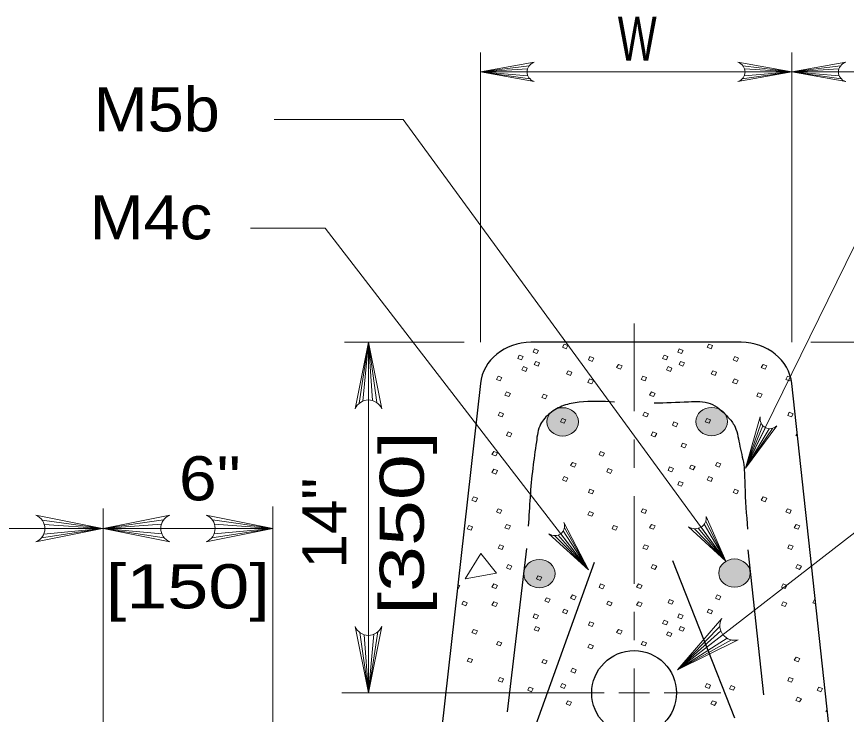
# Model space of a CAD drawing. Extents: x 1083.1 to 1123, y 697.4 to 741.4.
# Drawn here: x 1091.119 to 1094.054, y 706.055 to 708.522 of the extents above; entities that cross this region are included whole.
import ezdxf
from ezdxf.enums import TextEntityAlignment as Align

# ---------------------------------------------------------------- set-up
doc = ezdxf.new("R2010")
doc.units = 0
doc.header["$LTSCALE"] = 0.062
doc.linetypes.add('DOT_DASHED', pattern=[7.7, 5, -1.2, 0.3, -1.2])
doc.layers.add('1', color=7, linetype='Continuous', lineweight=13)

msp = doc.modelspace()

# ---------------------------------------------------------------- hatches: boundary and pattern name
at = {"layer": '1'}
h = msp.add_hatch(color=256, dxfattribs=at)
edge = h.paths.add_edge_path()
edge.add_ellipse((1093.05029, 707.08925), major_axis=(0.05572, 0), ratio=0.8999053, start_angle=0, end_angle=360)
h = msp.add_hatch(color=256, dxfattribs=at)
edge = h.paths.add_edge_path()
edge.add_ellipse((1093.57724, 707.09022), major_axis=(0.05572, 0), ratio=0.8999053, start_angle=0, end_angle=360)
h = msp.add_hatch(color=256, dxfattribs=at)
edge = h.paths.add_edge_path()
edge.add_ellipse((1092.96803, 706.55274), major_axis=(0.05572, 0), ratio=0.8999053, start_angle=0, end_angle=360)
h = msp.add_hatch(color=256, dxfattribs=at)
edge = h.paths.add_edge_path()
edge.add_ellipse((1093.65788, 706.55452), major_axis=(0.05572, 0), ratio=0.8999053, start_angle=0, end_angle=360)

# ---------------------------------------------------------------- linework, layer by layer
for p, q in [((1092.759, 707.3705), (1092.759, 708.39542)), ((1093.86025, 707.3705), (1093.86025, 708.39542)), ((1092.93175, 708.34817), (1092.759, 708.32642)), ((1092.92592, 708.33742), (1092.759, 708.32642)), ((1093.6875, 708.34817), (1093.86025, 708.32642)), ((1093.69333, 708.33742), (1093.86025, 708.32642)), ((1094.033, 708.34817), (1093.86025, 708.32642)), ((1094.02717, 708.33742), (1093.86025, 708.32642)), ((1092.92417, 708.32642), (1092.759, 708.32642)), ((1092.92717, 708.3125), (1092.759, 708.32642)), ((1092.93383, 708.30242), (1092.759, 708.32642)), ((1093.68542, 708.30242), (1093.86025, 708.32642)), ((1093.69208, 708.3125), (1093.86025, 708.32642)), ((1093.69508, 708.32642), (1093.86025, 708.32642)), ((1094.02533, 708.32642), (1093.86025, 708.32642)), ((1094.02842, 708.3125), (1093.86025, 708.32642)), ((1094.035, 708.30242), (1093.86025, 708.32642)), ((1092.02992, 708.158), (1092.48667, 708.158)), ((1093.62725, 706.59642), (1092.48667, 708.158)), ((1093.45608, 706.21192), (1095.83508, 708.05542)), ((1092.21067, 707.77358), (1091.94575, 707.77358)), ((1093.141, 706.5665), (1092.21067, 707.77358)), ((1092.70183, 707.3705), (1092.27875, 707.3705)), ((1092.33, 707.15475), (1092.363, 707.3705)), ((1092.34383, 707.16292), (1092.363, 707.3705)), ((1092.363, 706.13058), (1092.363, 707.3705)), ((1092.363, 707.16667), (1092.363, 707.3705)), ((1092.37808, 707.16442), (1092.363, 707.3705)), ((1092.39283, 707.15725), (1092.363, 707.3705)), ((1093.92825, 707.3705), (1096.348, 707.3705)), ((1093.84525, 707.25058), (1093.851, 707.2485)), ((1093.75167, 707.08575), (1093.69625, 706.92575)), ((1093.75833, 707.07567), (1093.69625, 706.92575)), ((1093.767, 707.069), (1093.69625, 706.92575)), ((1093.79175, 707.06617), (1093.69625, 706.92575)), ((1093.78033, 707.06508), (1093.69625, 706.92575)), ((1091.42492, 704.693), (1091.42492, 706.78342)), ((1092.02483, 704.99242), (1092.02483, 706.78958)), ((1091.20958, 706.74158), (1091.42292, 706.71175)), ((1091.21683, 706.72683), (1091.42292, 706.71175)), ((1091.63825, 706.74233), (1091.42492, 706.7125)), ((1091.631, 706.7275), (1091.42492, 706.7125)), ((1091.8115, 706.74233), (1092.02483, 706.7125)), ((1091.81875, 706.7275), (1092.02483, 706.7125)), ((1093.53975, 706.71725), (1093.62725, 706.59642)), ((1093.55067, 706.72692), (1093.62725, 706.59642)), ((1093.55633, 706.737), (1093.62725, 706.59642)), ((1091.42292, 706.71175), (1087.15183, 706.71308)), ((1091.20708, 706.67883), (1091.42292, 706.71175)), ((1091.21525, 706.69258), (1091.42292, 706.71175)), ((1091.21908, 706.71175), (1091.42292, 706.71175)), ((1091.42492, 706.7125), (1092.02483, 706.7125)), ((1091.62883, 706.7125), (1091.42492, 706.7125)), ((1091.63258, 706.69333), (1091.42492, 706.7125)), ((1091.64075, 706.6795), (1091.42492, 706.7125)), ((1091.809, 706.6795), (1092.02483, 706.7125)), ((1091.81717, 706.69333), (1092.02483, 706.7125)), ((1091.821, 706.7125), (1092.02483, 706.7125)), ((1093.022, 706.68667), (1093.141, 706.5665)), ((1093.03375, 706.6885), (1093.141, 706.5665)), ((1093.04333, 706.6935), (1093.141, 706.5665)), ((1093.05233, 706.70408), (1093.141, 706.5665)), ((1093.05617, 706.71508), (1093.141, 706.5665)), ((1093.51608, 706.71142), (1093.62725, 706.59642)), ((1093.52883, 706.71283), (1093.62725, 706.59642)), ((1093.94042, 706.46108), (1093.94367, 706.45967)), ((1093.60642, 706.36617), (1093.45608, 706.21192)), ((1092.33317, 706.34392), (1092.363, 706.13058)), ((1092.34792, 706.33667), (1092.363, 706.13058)), ((1092.396, 706.34642), (1092.363, 706.13058)), ((1092.38217, 706.33825), (1092.363, 706.13058)), ((1092.363, 706.3345), (1092.363, 706.13058)), ((1093.60975, 706.35008), (1093.45608, 706.21192)), ((1093.61725, 706.33683), (1093.45608, 706.21192)), ((1093.63192, 706.324), (1093.45608, 706.21192)), ((1093.64683, 706.31808), (1093.45608, 706.21192)), ((1093.19725, 706.13058), (1092.26917, 706.13058)), ((1093.357, 706.13058), (1093.24842, 706.13058)), ((1093.6095, 706.13058), (1093.4095, 706.13058))]:
    msp.add_line(p, q, dxfattribs=at)
at = {"layer": '1', "linetype": 'DOT_DASHED'}
msp.add_line((1093.30267, 707.43708), (1093.30267, 704.80367), dxfattribs=at)
at = {"layer": '1', "lineweight": 25}
for p, q in [((1093.68158, 707.3705), (1092.93775, 707.3705)), ((1092.92267, 706.64133), (1092.854, 706.06392)), ((1093.70475, 706.63675), (1093.76025, 706.12408)), ((1093.16208, 706.59233), (1092.73708, 705.41425)), ((1093.65925, 706.04117), (1093.43958, 706.5975))]:
    msp.add_line(p, q, dxfattribs=at)
at = {"layer": '1'}
for points in [[(1092.94983, 708.29208), (1092.759, 708.32642), (1092.94983, 708.36083)], [(1093.66942, 708.29208), (1093.86025, 708.32642), (1093.66942, 708.36083)], [(1094.05108, 708.29208), (1093.86025, 708.32642), (1094.05108, 708.36083)], [(1095.16083, 708.32642), (1093.50392, 708.32642), (1092.759, 708.32642)], [(1093.70142, 706.93558), (1094.084, 707.71383), (1094.26242, 707.71383)], [(1092.31592, 707.13492), (1092.363, 707.3705), (1092.41008, 707.13492)], [(1093.85508, 707.23808), (1093.85333, 707.23442), (1093.83983, 707.23925), (1093.84525, 707.25058)], [(1093.80742, 707.07525), (1093.69625, 706.92575), (1093.74858, 707.10725)], [(1093.88042, 707.03925), (1093.87492, 707.04125), (1093.87925, 707.04983)], [(1091.18733, 706.66467), (1091.42292, 706.71175), (1091.18733, 706.75892)], [(1091.6605, 706.66533), (1091.42492, 706.7125), (1091.6605, 706.75958)], [(1091.78925, 706.66533), (1092.02483, 706.7125), (1091.78925, 706.75958)], [(1093.55717, 706.75417), (1093.62725, 706.59642), (1093.49508, 706.718)], [(1093.05475, 706.73342), (1093.141, 706.5665), (1093.0015, 706.69325)], [(1092.67933, 706.51308), (1092.68592, 706.51033), (1092.68058, 706.499), (1092.67792, 706.5)], [(1093.94517, 706.44533), (1093.93508, 706.44892), (1093.94042, 706.46108)], [(1093.67117, 706.319), (1093.45608, 706.21192), (1093.61342, 706.3935)], [(1092.41008, 706.36625), (1092.363, 706.13058), (1092.31592, 706.36625)], [(1093.98692, 706.0625), (1093.98083, 706.06508), (1093.98558, 706.075)]]:
    msp.add_lwpolyline(points, dxfattribs=at)
for points in [[(1093.055, 707.3645), (1093.0685, 707.35892), (1093.06308, 707.34758), (1093.04958, 707.35325)], [(1093.56683, 707.3645), (1093.58033, 707.35892), (1093.57492, 707.34758), (1093.5615, 707.35325)], [(1092.95083, 707.34758), (1092.96433, 707.34192), (1092.95892, 707.33058), (1092.94542, 707.33542)], [(1093.46267, 707.34758), (1093.47617, 707.34192), (1093.47075, 707.33058), (1093.45733, 707.33542)], [(1092.89692, 707.32492), (1092.91042, 707.32008), (1092.905, 707.30875), (1092.89158, 707.31367)], [(1092.95533, 707.30308), (1092.96883, 707.2975), (1092.96342, 707.28617), (1092.94992, 707.29183)], [(1093.14658, 707.32008), (1093.16008, 707.31442), (1093.15467, 707.30308), (1093.14125, 707.308)], [(1093.40883, 707.32492), (1093.42233, 707.32008), (1093.41692, 707.30875), (1093.40342, 707.31367)], [(1093.46717, 707.30308), (1093.48067, 707.2975), (1093.47525, 707.28617), (1093.46183, 707.29183)], [(1093.6585, 707.32008), (1093.67192, 707.31442), (1093.66658, 707.30308), (1093.65308, 707.308)], [(1092.91133, 707.2845), (1092.92483, 707.27892), (1092.91942, 707.26758), (1092.90592, 707.27325)], [(1093.24717, 707.29258), (1093.26067, 707.28775), (1093.25433, 707.27567), (1093.24092, 707.28133)], [(1093.42317, 707.2845), (1093.43667, 707.27892), (1093.43125, 707.26758), (1093.41783, 707.27325)], [(1093.759, 707.29258), (1093.7725, 707.28775), (1093.76625, 707.27567), (1093.75275, 707.28133)], [(1092.8215, 707.25058), (1092.835, 707.24575), (1092.82958, 707.23442), (1092.81617, 707.23925)], [(1093.06933, 707.27), (1093.08283, 707.26517), (1093.0775, 707.253), (1093.064, 707.25867)], [(1093.33342, 707.25058), (1093.34683, 707.24575), (1093.3415, 707.23442), (1093.328, 707.23925)], [(1093.58125, 707.27), (1093.59467, 707.26517), (1093.58933, 707.253), (1093.57583, 707.25867)], [(1093.14567, 707.24092), (1093.15917, 707.23525), (1093.15292, 707.22392), (1093.13942, 707.22875)], [(1093.65758, 707.24092), (1093.671, 707.23525), (1093.66475, 707.22392), (1093.65125, 707.22875)], [(1092.85208, 707.19483), (1092.8655, 707.19), (1092.85925, 707.17867), (1092.84575, 707.1835)], [(1092.98225, 707.18675), (1092.99575, 707.18192), (1092.98942, 707.17058), (1092.976, 707.17542)], [(1093.36392, 707.19483), (1093.37742, 707.19), (1093.37108, 707.17867), (1093.35767, 707.1835)], [(1093.742, 707.19158), (1093.75542, 707.18675), (1093.75008, 707.17542), (1093.73658, 707.18025)], [(1092.82783, 707.12292), (1092.84125, 707.11808), (1092.83592, 707.10675), (1092.82242, 707.11158)], [(1093.04783, 707.10108), (1093.06133, 707.09625), (1093.05592, 707.08408), (1093.04242, 707.08975)], [(1093.33967, 707.12292), (1093.35317, 707.11808), (1093.34775, 707.10675), (1093.33425, 707.11158)], [(1093.55967, 707.10108), (1093.57317, 707.09625), (1093.56775, 707.08408), (1093.55433, 707.08975)], [(1093.8515, 707.12292), (1093.865, 707.11808), (1093.85958, 707.10675), (1093.84617, 707.11158)], [(1093.44383, 707.089), (1093.45733, 707.08333), (1093.45192, 707.072), (1093.43842, 707.07767)], [(1092.85742, 707.05342), (1092.87092, 707.04775), (1092.86467, 707.03642), (1092.85117, 707.04125)], [(1093.36933, 707.05342), (1093.38275, 707.04775), (1093.3765, 707.03642), (1093.363, 707.04125)], [(1093.47442, 707.01383), (1093.48783, 707.009), (1093.48242, 706.99683), (1093.469, 707.0025)], [(1092.80625, 706.98475), (1092.81975, 706.97983), (1092.81342, 706.96858), (1092.8, 706.97342)], [(1093.18433, 706.98475), (1093.19775, 706.97908), (1093.19242, 706.96775), (1093.17892, 706.97258)], [(1092.80625, 706.92167), (1092.81975, 706.91683), (1092.81342, 706.90475), (1092.8, 706.91033)], [(1093.08467, 706.94592), (1093.09808, 706.94025), (1093.09183, 706.92892), (1093.07833, 706.93458)], [(1093.21125, 706.92408), (1093.22475, 706.9185), (1093.21933, 706.90717), (1093.20583, 706.91283)], [(1093.42858, 706.92975), (1093.44208, 706.92408), (1093.43667, 706.91283), (1093.42317, 706.91767)], [(1093.50492, 706.93625), (1093.51842, 706.93142), (1093.51208, 706.91925), (1093.49858, 706.92492)], [(1093.5965, 706.94592), (1093.61, 706.94025), (1093.60367, 706.92892), (1093.59025, 706.93458)], [(1093.055, 706.89583), (1093.0685, 706.89017), (1093.06308, 706.87883), (1093.04958, 706.8845)], [(1093.56683, 706.89583), (1093.58033, 706.89017), (1093.57492, 706.87883), (1093.5615, 706.8845)], [(1093.46267, 706.87883), (1093.47617, 706.87317), (1093.47075, 706.86192), (1093.45733, 706.86675)], [(1093.14658, 706.85133), (1093.16008, 706.84575), (1093.15467, 706.83442), (1093.14125, 706.83925)], [(1093.6585, 706.85133), (1093.67192, 706.84575), (1093.66658, 706.83442), (1093.65308, 706.83925)], [(1092.73533, 706.82392), (1092.74875, 706.81908), (1092.7425, 706.80692), (1092.729, 706.81258)], [(1093.759, 706.82392), (1093.7725, 706.81908), (1093.76625, 706.80692), (1093.75275, 706.81258)], [(1092.8215, 706.78192), (1092.835, 706.777), (1092.82958, 706.76575), (1092.81617, 706.77058)], [(1093.33342, 706.78192), (1093.34683, 706.777), (1093.3415, 706.76575), (1093.328, 706.77058)], [(1093.84525, 706.78192), (1093.85875, 706.777), (1093.85333, 706.76575), (1093.83983, 706.77058)], [(1093.14567, 706.77217), (1093.15917, 706.7665), (1093.15292, 706.75525), (1093.13942, 706.76008)], [(1092.71825, 706.72292), (1092.73175, 706.718), (1092.72633, 706.70675), (1092.71283, 706.71158)], [(1092.85208, 706.72617), (1092.8655, 706.72125), (1092.85925, 706.71), (1092.84575, 706.71483)], [(1093.23008, 706.72292), (1093.24358, 706.718), (1093.23817, 706.70675), (1093.22475, 706.71158)], [(1093.36392, 706.72617), (1093.37742, 706.72125), (1093.37108, 706.71), (1093.35767, 706.71483)], [(1093.87575, 706.72617), (1093.88925, 706.72125), (1093.883, 706.71), (1093.8695, 706.71483)], [(1092.82783, 706.65417), (1092.84125, 706.64933), (1092.83592, 706.63808), (1092.82242, 706.64292)], [(1093.33967, 706.65417), (1093.35317, 706.64933), (1093.34775, 706.63808), (1093.33425, 706.64292)], [(1093.8515, 706.65417), (1093.865, 706.64933), (1093.85958, 706.63808), (1093.84617, 706.64292)], [(1092.76133, 706.62433), (1092.70567, 706.53458), (1092.81617, 706.554)], [(1092.85742, 706.58467), (1092.87092, 706.57908), (1092.86467, 706.56775), (1092.85117, 706.57258)], [(1093.36933, 706.58467), (1093.38275, 706.57908), (1093.3765, 706.56775), (1093.363, 706.57258)], [(1093.88117, 706.58467), (1093.89467, 706.57908), (1093.88833, 706.56775), (1093.87492, 706.57258)], [(1092.9625, 706.54508), (1092.976, 706.54025), (1092.97058, 706.52817), (1092.95717, 706.53383)], [(1092.80625, 706.516), (1092.81975, 706.51117), (1092.81342, 706.49983), (1092.8, 706.50467)], [(1093.18433, 706.516), (1093.19775, 706.51033), (1093.19242, 706.499), (1093.17892, 706.50392)], [(1093.31808, 706.516), (1093.33158, 706.51117), (1093.32533, 706.49983), (1093.31183, 706.50467)], [(1093.83, 706.516), (1093.84342, 706.51117), (1093.83717, 706.49983), (1093.82367, 706.50467)], [(1092.69942, 706.45542), (1092.71283, 706.44975), (1092.7075, 706.43842), (1092.694, 706.44408)], [(1092.80625, 706.453), (1092.81975, 706.44817), (1092.81342, 706.436), (1092.8, 706.44167)], [(1092.99308, 706.4675), (1093.0065, 706.46267), (1093.00025, 706.45058), (1092.98675, 706.45617)], [(1093.08467, 706.47725), (1093.09808, 706.47158), (1093.09183, 706.46025), (1093.07833, 706.46592)], [(1093.21125, 706.45542), (1093.22475, 706.44975), (1093.21933, 706.43842), (1093.20583, 706.44408)], [(1093.31808, 706.453), (1093.33158, 706.44817), (1093.32533, 706.436), (1093.31183, 706.44167)], [(1093.42858, 706.46108), (1093.44208, 706.45542), (1093.43667, 706.44408), (1093.42317, 706.44892)], [(1093.5965, 706.47725), (1093.61, 706.47158), (1093.60367, 706.46025), (1093.59025, 706.46592)], [(1093.83, 706.453), (1093.84342, 706.44817), (1093.83717, 706.436), (1093.82367, 706.44167)], [(1093.055, 706.42708), (1093.0685, 706.4215), (1093.06308, 706.41017), (1093.04958, 706.41583)], [(1093.56683, 706.42708), (1093.58033, 706.4215), (1093.57492, 706.41017), (1093.5615, 706.41583)], [(1092.95083, 706.41017), (1092.96433, 706.4045), (1092.95892, 706.39317), (1092.94542, 706.398)], [(1093.46267, 706.41017), (1093.47617, 706.4045), (1093.47075, 706.39317), (1093.45733, 706.398)], [(1092.95533, 706.36567), (1092.96883, 706.36008), (1092.96342, 706.34875), (1092.94992, 706.35442)], [(1093.14658, 706.38267), (1093.16008, 706.377), (1093.15467, 706.36567), (1093.14125, 706.37058)], [(1093.40883, 706.3875), (1093.42233, 706.38267), (1093.41692, 706.37133), (1093.40342, 706.37617)], [(1093.46717, 706.36567), (1093.48067, 706.36008), (1093.47525, 706.34875), (1093.46183, 706.35442)], [(1092.73533, 706.35517), (1092.74875, 706.35033), (1092.7425, 706.33825), (1092.729, 706.34392)], [(1093.24717, 706.35517), (1093.26067, 706.35033), (1093.25433, 706.33825), (1093.24092, 706.34392)], [(1093.42317, 706.34708), (1093.43667, 706.3415), (1093.43125, 706.33017), (1093.41783, 706.33583)], [(1092.8215, 706.31317), (1092.835, 706.30833), (1092.82958, 706.297), (1092.81617, 706.30183)], [(1093.33342, 706.31317), (1093.34683, 706.30833), (1093.3415, 706.297), (1093.328, 706.30183)], [(1093.14567, 706.3035), (1093.15917, 706.29783), (1093.15292, 706.2865), (1093.13942, 706.29133)], [(1092.71825, 706.25417), (1092.73175, 706.24933), (1092.72633, 706.238), (1092.71283, 706.24283)], [(1092.98225, 706.24933), (1092.99575, 706.2445), (1092.98942, 706.23317), (1092.976, 706.238)], [(1093.87575, 706.25742), (1093.88925, 706.25258), (1093.883, 706.24125), (1093.8695, 706.24608)], [(1093.08467, 706.21783), (1093.09808, 706.213), (1093.09275, 706.20083), (1093.07925, 706.2065)], [(1092.82783, 706.1855), (1092.84125, 706.18067), (1092.83592, 706.16933), (1092.82242, 706.17417)], [(1093.04783, 706.16367), (1093.06133, 706.15883), (1093.05592, 706.14667), (1093.04242, 706.15233)], [(1093.55967, 706.16367), (1093.57317, 706.15883), (1093.56775, 706.14667), (1093.55433, 706.15233)], [(1093.8515, 706.1855), (1093.865, 706.18067), (1093.85958, 706.16933), (1093.84617, 706.17417)], [(1092.932, 706.15158), (1092.94542, 706.14592), (1092.94008, 706.13458), (1092.92658, 706.14025)], [(1093.64592, 706.15717), (1093.65933, 706.15158), (1093.654, 706.14025), (1093.6405, 706.14508)], [(1093.95567, 706.15158), (1093.96917, 706.14592), (1093.96375, 706.13458), (1093.95033, 706.14025)], [(1093.0685, 706.10308), (1093.08192, 706.09825), (1093.07567, 706.08692), (1093.06217, 706.09175)], [(1093.58033, 706.10308), (1093.59383, 706.09825), (1093.5875, 706.08692), (1093.57408, 706.09175)], [(1093.88117, 706.116), (1093.89467, 706.11033), (1093.88833, 706.099), (1093.87492, 706.10383)]]:
    msp.add_lwpolyline(points, close=True, dxfattribs=at)
at = {"layer": '1', "lineweight": 25}
for points in [[(1092.759, 707.22517), (1092.58783, 705.69442), (1092.046, 704.92958)], [(1094.57242, 704.93058), (1094.02833, 705.68267), (1093.86025, 707.22475)]]:
    msp.add_lwpolyline(points, dxfattribs=at)
msp.add_circle((1093.30275, 706.13058), 0.14994, dxfattribs=at)
at = {"layer": '1'}
for centre, start, end in [((1092.36306, 707.1159), 22.08782, 157.91395), ((1091.1683, 706.71186), 292.08605, 67.91218), ((1091.67957, 706.71248), 112.08782, 247.91395), ((1091.77021, 706.71248), 292.08605, 67.91218), ((1093.6573, 706.36793), 149.85926, 285.68538), ((1092.36296, 706.38524), 202.08782, 337.91395)]:
    msp.add_arc(centre, 0.05085, start, end, dxfattribs=at)
for centre, major_axis, ratio, start_param, end_param in [((1092.96526, 708.32649), (-0.04119, 0), 0.9, 5.0978942, 7.4685073), ((1093.65401, 708.32649), (0.04119, 0), 0.9, 5.0978633, 7.4684764), ((1094.06648, 708.32649), (-0.04119, 0), 0.9, 5.0978942, 7.4685073), ((1093.78464, 707.10469), (-0.01122, -0.03837), 0.899905, 4.9046515, 7.2752647), ((1093.51791, 706.74744), (-0.03997, 0), 0.899905, 0.9629996, 3.3336128), ((1093.01895, 706.72525), (0.02552, -0.03077), 0.899905, 5.0568214, 7.4274346)]:
    msp.add_ellipse(centre, major_axis=major_axis, ratio=ratio, start_param=start_param, end_param=end_param, dxfattribs=at)
at = {"layer": '1', "lineweight": 25}
for centre, start_param, end_param in [((1092.93775, 707.20889), 1.5707963, 3.0409871), ((1093.68154, 707.20889), 0.0980063, 1.5707963)]:
    msp.add_ellipse(centre, major_axis=(0.1796, 0), ratio=0.899905, start_param=start_param, end_param=end_param, dxfattribs=at)
at = {"layer": '1'}
for centre in [(1093.05029, 707.08925), (1093.57724, 707.09022), (1092.96803, 706.55274), (1093.65788, 706.55452)]:
    msp.add_ellipse(centre, major_axis=(0.05572, 0), ratio=0.899905, dxfattribs=at)
at = {"layer": '1', "lineweight": 25}
for points in [[(1093.23325, 707.15942), (1093.10833, 707.15842), (1093.05367, 707.14675), (1093.00508, 707.11933), (1092.97233, 707.08125), (1092.95717, 707.01883), (1092.9445, 706.92508), (1092.92858, 706.72067)], [(1093.374, 707.156), (1093.49575, 707.16025), (1093.57242, 707.15375), (1093.63125, 707.11), (1093.65625, 707.07825), (1093.67517, 707.01208), (1093.69058, 706.93675), (1093.6945, 706.8635), (1093.70408, 706.70983)]]:
    msp.add_spline(points, degree=3, dxfattribs=at)

# ---------------------------------------------------------------- texts
at = {"layer": '1'}
for s, width, p in [('W', 0.7, (1093.24508, 708.36608)), ('M5b', 1.1, (1091.39108, 708.11617)), ('M4c', 1.1, (1091.37708, 707.73467))]:
    msp.add_text(s, height=0.156, dxfattribs=dict(at, width=width)).set_placement(p)
for s, width, p in [('[350]', 1.4, (1092.55925, 706.73125)), ('14"', 1.05, (1092.28525, 706.73125))]:
    msp.add_text(s, height=0.156, rotation=90, dxfattribs=dict(at, width=width)).set_placement(p, align=Align.CENTER)
for s, width, p in [('6"', 1.15, (1091.80233, 706.81167)), ('[150]', 1.25, (1091.72433, 706.42983))]:
    msp.add_text(s, height=0.156, dxfattribs=dict(at, width=width)).set_placement(p, align=Align.CENTER)

doc.saveas('drawing.dxf')
